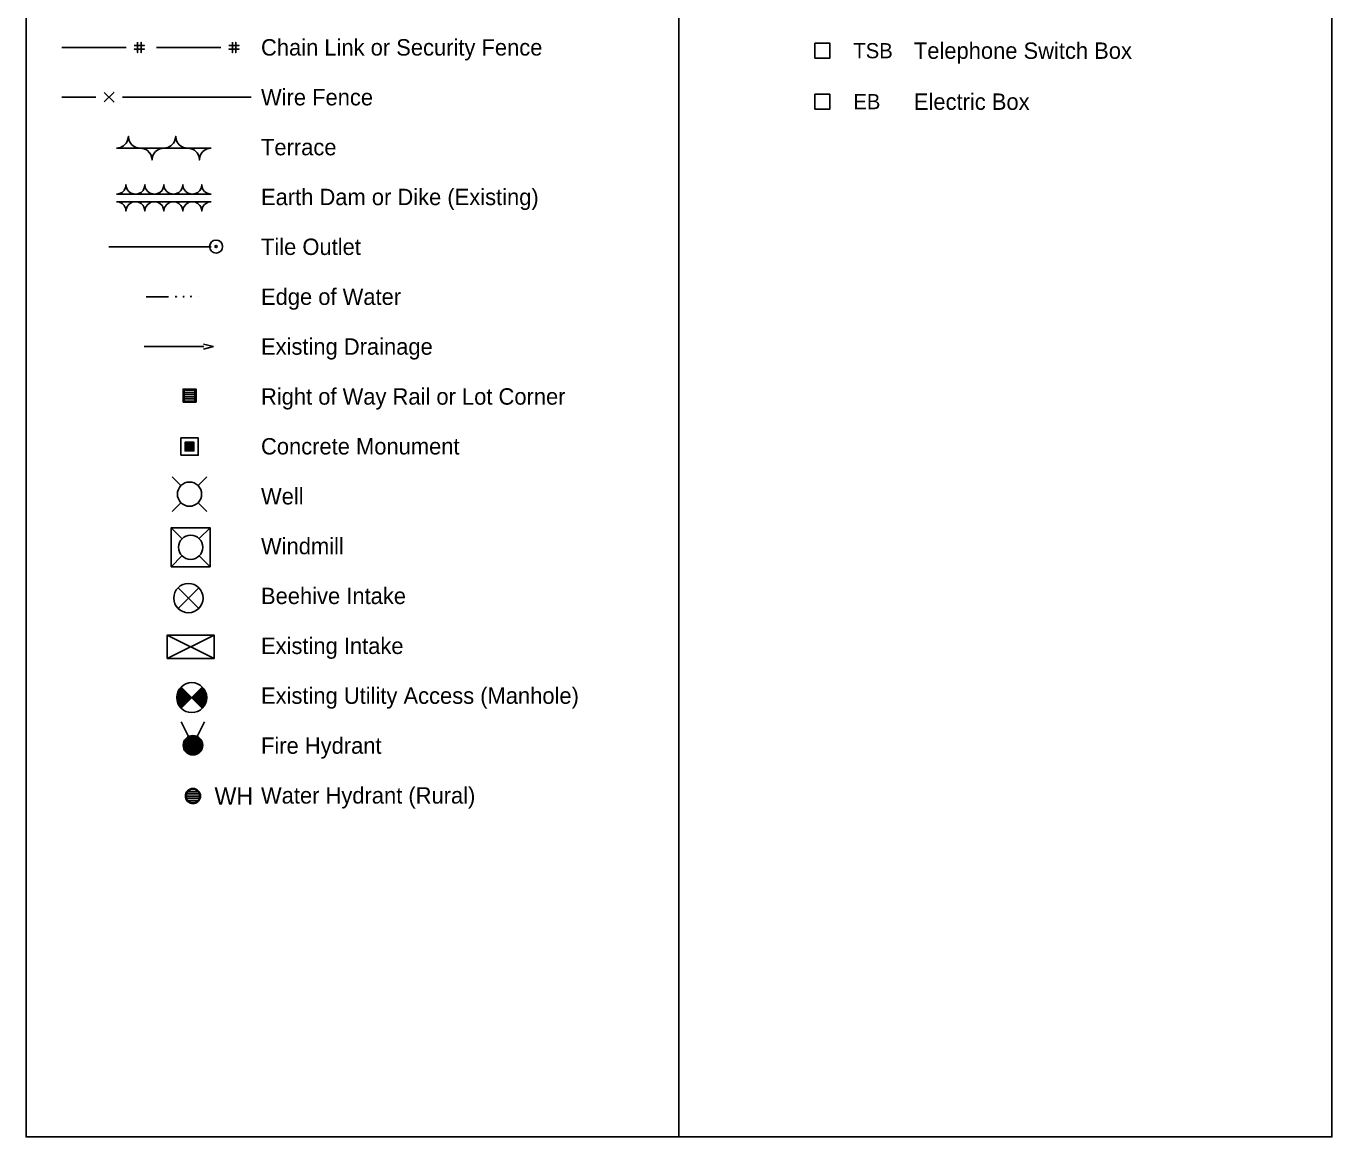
# Model space of a CAD drawing. Extents: x 6082259 to 6083454, y 5964102 to 5966092.
# Drawn here: x 6082259 to 6083454, y 5964102 to 5965119 of the extents above; entities that cross this region are included whole.
import ezdxf

# ---------------------------------------------------------------- set-up
doc = ezdxf.new("R2010")
doc.units = 0
for name, color, linetype in [('Default', 7, 'Continuous'), ('Level 20', 7, 'Continuous'), ('Text', 7, 'Continuous')]:
    doc.layers.add(name, color=color, linetype=linetype)

msp = doc.modelspace()

# ---------------------------------------------------------------- linework, layer by layer
at = {"layer": 'Default'}
for points in [[(6082259, 5966092.2), (6082856.5, 5966092.2), (6082856.5, 5964102.2), (6082259, 5964102.2)], [(6082856.5, 5966092.2), (6083454, 5966092.2), (6083454, 5964102.2), (6082856.5, 5964102.2)]]:
    msp.add_lwpolyline(points, close=True, dxfattribs=at)
at = {"layer": 'Level 20'}
for p, q in [((6082334.7, 5964916.8), (6082428.3, 5964916.8)), ((6082369, 5964871.1), (6082389.5, 5964871.1)), ((6082410, 5964871.1), (6082410, 5964871.1)), ((6082417, 5964871.3), (6082417, 5964871.3)), ((6082367, 5964825.4), (6082421.8, 5964825.4)), ((6082421.5, 5964827.8), (6082430.6, 5964825.5)), ((6082430.6, 5964825.5), (6082421.5, 5964823.2)), ((6082392.8, 5964706.1), (6082400.7, 5964698.3)), ((6082416.5, 5964698.3), (6082424.4, 5964706.1)), ((6082392.8, 5964674.6), (6082400.7, 5964682.5)), ((6082416.5, 5964682.5), (6082424.4, 5964674.6)), ((6082391.8, 5964659.7), (6082401.7, 5964649.7)), ((6082417.5, 5964649.7), (6082427.4, 5964659.7)), ((6082391.8, 5964624), (6082401.7, 5964634)), ((6082417.5, 5964634), (6082427.4, 5964624)), ((6082398.2, 5964585.8), (6082417.1, 5964604.7)), ((6082398.2, 5964604.7), (6082417.1, 5964585.8)), ((6082400.9, 5964494.5), (6082420.3, 5964513.9)), ((6082400.9, 5964513.9), (6082420.3, 5964494.5)), ((6082401, 5964482), (6082411.7, 5964460.6)), ((6082411.7, 5964460.6), (6082422.4, 5964482))]:
    msp.add_line(p, q, dxfattribs=at)
for points in [[(6082291.6, 5965099.3), (6082350.5, 5965099.3)], [(6082361.1, 5965104), (6082361.1, 5965094.6), (6082361.1, 5965097.8), (6082358, 5965097.8), (6082367.3, 5965097.8), (6082364.2, 5965097.8), (6082364.2, 5965094.6), (6082364.2, 5965104), (6082364.2, 5965100.9), (6082367.3, 5965100.9), (6082358, 5965100.9)], [(6082378.3, 5965099.3), (6082437.2, 5965099.3)], [(6082447.8, 5965104), (6082447.8, 5965094.6), (6082447.8, 5965097.8), (6082444.7, 5965097.8), (6082454, 5965097.8), (6082450.9, 5965097.8), (6082450.9, 5965094.6), (6082450.9, 5965104), (6082450.9, 5965100.9), (6082454, 5965100.9), (6082444.7, 5965100.9)], [(6082987.8, 5965089.5), (6082987.8, 5965089.5), (6082994.6, 5965089.5), (6082994.6, 5965103.1), (6082981, 5965103.1), (6082981, 5965089.5), (6082987.8, 5965089.5)], [(6082330.6, 5965049.4), (6082339.3, 5965058), (6082334.9, 5965053.7), (6082339.3, 5965049.4), (6082330.6, 5965058)], [(6082291.6, 5965053.7), (6082322.8, 5965053.7)], [(6082347.1, 5965053.7), (6082464.9, 5965053.7)], [(6082987.8, 5965042.8), (6082987.8, 5965042.8), (6082994.6, 5965042.8), (6082994.6, 5965056.4), (6082981, 5965056.4), (6082981, 5965042.8), (6082987.8, 5965042.8)], [(6082341.8, 5965007.1), (6082345.4, 5965007.7), (6082348.1, 5965009.2), (6082350.5, 5965011.5), (6082351.5, 5965013.1), (6082352.2, 5965015.2), (6082352.6, 5965018), (6082353, 5965014.9), (6082354, 5965012.6), (6082355.9, 5965010.2), (6082357.9, 5965008.7), (6082359.8, 5965007.8), (6082363.4, 5965007.1)], [(6082385.1, 5965007.1), (6082388.7, 5965007.7), (6082391.5, 5965009.2), (6082393.8, 5965011.5), (6082394.8, 5965013.1), (6082395.6, 5965015.2), (6082396, 5965018), (6082396.4, 5965014.9), (6082397.4, 5965012.6), (6082399.2, 5965010.2), (6082401.2, 5965008.7), (6082403.2, 5965007.8), (6082406.8, 5965007.1)], [(6082341.8, 5965007.1), (6082428.5, 5965007.1)], [(6082363.4, 5965007.1), (6082367, 5965006.5), (6082369.8, 5965005.1), (6082372.1, 5965002.8), (6082373.1, 5965001.2), (6082373.9, 5964999.1), (6082374.3, 5964996.3), (6082374.7, 5964999.3), (6082375.7, 5965001.7), (6082377.5, 5965004), (6082379.6, 5965005.6), (6082381.5, 5965006.5), (6082385.1, 5965007.1)], [(6082406.8, 5965007.1), (6082410.4, 5965006.5), (6082413.1, 5965005.1), (6082415.5, 5965002.8), (6082416.5, 5965001.2), (6082417.3, 5964999.1), (6082417.6, 5964996.3), (6082418.1, 5964999.3), (6082419, 5965001.7), (6082420.9, 5965004), (6082422.9, 5965005.6), (6082424.8, 5965006.5), (6082428.5, 5965007.1)], [(6082341.8, 5964965), (6082344.6, 5964965.5), (6082346.8, 5964966.6), (6082348.7, 5964968.4), (6082349.5, 5964969.7), (6082350.2, 5964971.4), (6082350.4, 5964973.6), (6082350.8, 5964971.2), (6082351.6, 5964969.3), (6082353, 5964967.4), (6082354.7, 5964966.2), (6082356.2, 5964965.5), (6082359.1, 5964965)], [(6082341.8, 5964965), (6082428.5, 5964965)], [(6082359.1, 5964965), (6082362, 5964965.5), (6082364.2, 5964966.6), (6082366.1, 5964968.4), (6082366.9, 5964969.7), (6082367.5, 5964971.4), (6082367.8, 5964973.6), (6082368.1, 5964971.2), (6082368.9, 5964969.3), (6082370.4, 5964967.4), (6082372, 5964966.2), (6082373.5, 5964965.5), (6082376.5, 5964965)], [(6082376.5, 5964965), (6082379.3, 5964965.5), (6082381.5, 5964966.6), (6082383.4, 5964968.4), (6082384.2, 5964969.7), (6082384.8, 5964971.4), (6082385.1, 5964973.6), (6082385.5, 5964971.2), (6082386.3, 5964969.3), (6082387.7, 5964967.4), (6082389.3, 5964966.2), (6082390.9, 5964965.5), (6082393.8, 5964965)], [(6082393.8, 5964965), (6082396.6, 5964965.5), (6082398.9, 5964966.6), (6082400.7, 5964968.4), (6082401.5, 5964969.7), (6082402.2, 5964971.4), (6082402.5, 5964973.6), (6082402.8, 5964971.2), (6082403.6, 5964969.3), (6082405.1, 5964967.4), (6082406.7, 5964966.2), (6082408.2, 5964965.5), (6082411.1, 5964965)], [(6082411.1, 5964965), (6082414, 5964965.5), (6082416.2, 5964966.6), (6082418.1, 5964968.4), (6082418.9, 5964969.7), (6082419.5, 5964971.4), (6082419.8, 5964973.6), (6082420.1, 5964971.2), (6082420.9, 5964969.3), (6082422.4, 5964967.4), (6082424, 5964966.2), (6082425.5, 5964965.5), (6082428.5, 5964965)], [(6082341.8, 5964958), (6082359.1, 5964958)], [(6082341.8, 5964958), (6082344.6, 5964957.5), (6082346.8, 5964956.4), (6082348.7, 5964954.6), (6082349.5, 5964953.3), (6082350.2, 5964951.6), (6082350.4, 5964949.4), (6082350.8, 5964951.8), (6082351.6, 5964953.7), (6082353, 5964955.6), (6082354.7, 5964956.8), (6082356.2, 5964957.5), (6082359.1, 5964958)], [(6082359.1, 5964958), (6082376.4, 5964958)], [(6082359.1, 5964958), (6082362, 5964957.5), (6082364.2, 5964956.4), (6082366.1, 5964954.6), (6082366.9, 5964953.3), (6082367.5, 5964951.6), (6082367.8, 5964949.4), (6082368.1, 5964951.8), (6082368.9, 5964953.7), (6082370.4, 5964955.6), (6082372, 5964956.8), (6082373.5, 5964957.5), (6082376.4, 5964958)], [(6082376.5, 5964958), (6082393.8, 5964958)], [(6082376.5, 5964958), (6082379.3, 5964957.5), (6082381.5, 5964956.4), (6082383.4, 5964954.6), (6082384.2, 5964953.3), (6082384.8, 5964951.6), (6082385.1, 5964949.4), (6082385.5, 5964951.8), (6082386.3, 5964953.7), (6082387.7, 5964955.6), (6082389.3, 5964956.8), (6082390.9, 5964957.5), (6082393.8, 5964958)], [(6082393.8, 5964958), (6082411.1, 5964958)], [(6082393.8, 5964958), (6082396.6, 5964957.5), (6082398.9, 5964956.4), (6082400.7, 5964954.6), (6082401.5, 5964953.3), (6082402.2, 5964951.6), (6082402.5, 5964949.4), (6082402.8, 5964951.8), (6082403.6, 5964953.7), (6082405.1, 5964955.6), (6082406.7, 5964956.8), (6082408.2, 5964957.5), (6082411.1, 5964958)], [(6082411.1, 5964958), (6082428.5, 5964958)], [(6082411.1, 5964958), (6082414, 5964957.5), (6082416.2, 5964956.4), (6082418.1, 5964954.6), (6082418.9, 5964953.3), (6082419.5, 5964951.6), (6082419.8, 5964949.4), (6082420.1, 5964951.8), (6082420.9, 5964953.7), (6082422.4, 5964955.6), (6082424, 5964956.8), (6082425.5, 5964957.5), (6082428.5, 5964958)], [(6082403.7, 5964775.6), (6082403.7, 5964785.5), (6082413.6, 5964785.5), (6082413.6, 5964775.6), (6082403.7, 5964775.6), (6082403.7, 5964777.5), (6082413.6, 5964777.5), (6082413.6, 5964779.5), (6082403.7, 5964779.5), (6082403.7, 5964781.5), (6082413.6, 5964781.5), (6082413.6, 5964783.5), (6082403.7, 5964783.5)], [(6082400.7, 5964726), (6082400.7, 5964741.9), (6082416.5, 5964741.9), (6082416.5, 5964726), (6082400.7, 5964726)], [(6082404.6, 5964730), (6082404.6, 5964737.9), (6082412.6, 5964737.9), (6082412.6, 5964730), (6082404.6, 5964730), (6082405.6, 5964731), (6082405.6, 5964736.9), (6082411.6, 5964736.9), (6082411.6, 5964731), (6082406.6, 5964731), (6082406.6, 5964735.9), (6082410.6, 5964735.9), (6082410.6, 5964732), (6082407.6, 5964732), (6082407.6, 5964734.9), (6082409.6, 5964734.9), (6082409.6, 5964733), (6082408.6, 5964733), (6082408.6, 5964734)], [(6082388.2, 5964540), (6082431, 5964561.4), (6082431, 5964540), (6082388.2, 5964561.4)], [(6082400.7, 5964495.3), (6082401.2, 5964495.3), (6082402.2, 5964496.3), (6082400.2, 5964496.3), (6082399.2, 5964497.3), (6082403.2, 5964497.3), (6082404.2, 5964498.3), (6082398.7, 5964498.3), (6082398.2, 5964499.3), (6082405.1, 5964499.3), (6082406.1, 5964500.3), (6082398.2, 5964500.3), (6082397.7, 5964501.2), (6082407.1, 5964501.2), (6082408.1, 5964502.2), (6082397.7, 5964502.2), (6082397.2, 5964503.2), (6082409.1, 5964503.2), (6082410.1, 5964504.2), (6082397.2, 5964504.2), (6082397.2, 5964505.2), (6082409.1, 5964505.2), (6082408.1, 5964506.2), (6082397.7, 5964506.2), (6082397.7, 5964507.2), (6082407.1, 5964507.2), (6082406.1, 5964508.2), (6082397.7, 5964508.2), (6082398.2, 5964509.2), (6082405.1, 5964509.2), (6082404.2, 5964510.2), (6082398.7, 5964510.2), (6082399.2, 5964511.1), (6082403.2, 5964511.1), (6082402.2, 5964512.1), (6082399.7, 5964512.1), (6082400.7, 5964513.1), (6082401.2, 5964513.1), (6082410.1, 5964504.2), (6082401.2, 5964495.3), (6082400.7, 5964495.3), (6082399.2, 5964497.3), (6082397.7, 5964501.2), (6082397.2, 5964505.2), (6082398.2, 5964509.2), (6082400.7, 5964513.1)], [(6082420.5, 5964495.3), (6082420, 5964495.3), (6082419, 5964496.3), (6082421, 5964496.3), (6082422, 5964497.3), (6082418, 5964497.3), (6082417, 5964498.3), (6082422.5, 5964498.3), (6082423, 5964499.3), (6082416, 5964499.3), (6082415, 5964500.3), (6082423, 5964500.3), (6082423.5, 5964501.2), (6082414.1, 5964501.2), (6082413.1, 5964502.2), (6082423.5, 5964502.2), (6082424, 5964503.2), (6082412.1, 5964503.2), (6082411.1, 5964504.2), (6082424, 5964504.2), (6082424, 5964505.2), (6082412.1, 5964505.2), (6082413.1, 5964506.2), (6082423.5, 5964506.2), (6082423.5, 5964507.2), (6082414.1, 5964507.2), (6082415, 5964508.2), (6082423.5, 5964508.2), (6082423, 5964509.2), (6082416, 5964509.2), (6082417, 5964510.2), (6082422.5, 5964510.2), (6082422, 5964511.1), (6082418, 5964511.1), (6082419, 5964512.1), (6082421.5, 5964512.1), (6082420.5, 5964513.1), (6082420, 5964513.1), (6082411.1, 5964504.2), (6082420, 5964495.3), (6082420.5, 5964495.3), (6082422, 5964497.3), (6082423.5, 5964501.2), (6082424, 5964505.2), (6082423, 5964509.2), (6082420.5, 5964513.1)], [(6082413.2, 5964469), (6082410.2, 5964469), (6082406.3, 5964467.1), (6082404.3, 5964464.6), (6082403.3, 5964461.1), (6082403.8, 5964457.7), (6082406.3, 5964454.2), (6082408.7, 5964452.7), (6082411.7, 5964452.2), (6082414.7, 5964452.7), (6082417.7, 5964454.7), (6082419.6, 5964457.7), (6082420.1, 5964460.6), (6082419.6, 5964463.6), (6082418.2, 5964466.1), (6082415.7, 5964468.1), (6082413.2, 5964469), (6082416.7, 5964467.6), (6082407.3, 5964467.6), (6082405.3, 5964466.1), (6082418.2, 5964466.1), (6082419.1, 5964464.6), (6082404.3, 5964464.6), (6082403.8, 5964463.1), (6082419.6, 5964463.1), (6082420.1, 5964461.6), (6082403.3, 5964461.6), (6082403.3, 5964460.1), (6082420.1, 5964460.1), (6082419.6, 5964458.6), (6082403.8, 5964458.6), (6082404.3, 5964457.2), (6082419.1, 5964457.2), (6082418.2, 5964455.7), (6082405.3, 5964455.7), (6082406.3, 5964454.2), (6082417.2, 5964454.2), (6082414.7, 5964452.7), (6082408.7, 5964452.7)], [(6082413.7, 5964420), (6082409.7, 5964420), (6082406.8, 5964418), (6082405.8, 5964416), (6082405.8, 5964412.1), (6082406.8, 5964410.1), (6082409.7, 5964408.1), (6082413.7, 5964408.1), (6082416.7, 5964410.1), (6082417.7, 5964412.1), (6082417.7, 5964416), (6082416.7, 5964418), (6082413.7, 5964420), (6082416.7, 5964418), (6082406.8, 5964418), (6082405.8, 5964416), (6082417.7, 5964416), (6082417.7, 5964414.1), (6082405.8, 5964414.1), (6082405.8, 5964412.1), (6082417.7, 5964412.1), (6082416.7, 5964410.1), (6082406.8, 5964410.1)]]:
    msp.add_lwpolyline(points, dxfattribs=at)
for points in [[(6082402.7, 5964774.6), (6082402.7, 5964786.5), (6082414.6, 5964786.5), (6082414.6, 5964774.6)], [(6082391.8, 5964624), (6082391.8, 5964659.7), (6082427.4, 5964659.7), (6082427.4, 5964624)], [(6082388.2, 5964540), (6082388.2, 5964561.4), (6082431, 5964561.4), (6082431, 5964540)]]:
    msp.add_lwpolyline(points, close=True, dxfattribs=at)
for centre, radius in [((6082432.9, 5964917), 5.94), ((6082432.9, 5964917), 0.991), ((6082396.3, 5964871.1), 0.342), ((6082403.2, 5964871.1), 0.342), ((6082410, 5964871.3), 0.342), ((6082408.6, 5964690.4), 11.1), ((6082409.6, 5964641.8), 11.1), ((6082407.6, 5964595.3), 13.4), ((6082410.6, 5964504.2), 13.7), ((6082411.7, 5964460.6), 8.92), ((6082411.7, 5964414.1), 6.93)]:
    msp.add_circle(centre, radius, dxfattribs=at)

# ---------------------------------------------------------------- texts
for s, height, p in [('TSB', 13.87, (6083016.1, 5965089.3)), ('EB', 13.87, (6083016.1, 5965042.7)), ('Well', 15, (6082474, 5964681)), ('WH', 15.85, (6082431.5, 5964406.1))]:
    msp.add_text(s, height=height, dxfattribs=at).set_placement(p)
at = {"layer": 'Text'}
for s, p in [('Chain Link or Security Fence', (6082474, 5965091.8)), ('Telephone Switch Box', (6083071.5, 5965088.8)), ('Wire Fence', (6082474, 5965046.2)), ('Electric Box', (6083071.5, 5965042.1)), ('Terrace', (6082474, 5965000.5)), ('Earth Dam or Dike (Existing)', (6082474, 5964954.9)), ('Tile Outlet', (6082474, 5964909.3)), ('Edge of Water', (6082474, 5964863.6)), ('Existing Drainage', (6082474, 5964818)), ('Right of Way Rail or Lot Corner', (6082474, 5964772.3)), ('Concrete Monument', (6082474, 5964726.7)), ('Windmill', (6082474, 5964635.4)), ('Beehive Intake', (6082474, 5964589.8)), ('Existing Intake', (6082474, 5964544.1)), ('Existing Utility Access (Manhole)', (6082474, 5964498.5)), ('Fire Hydrant', (6082474, 5964452.8)), ('Water Hydrant (Rural)', (6082474, 5964407.2))]:
    msp.add_text(s, height=15, dxfattribs=at).set_placement(p)

doc.saveas('drawing.dxf')
